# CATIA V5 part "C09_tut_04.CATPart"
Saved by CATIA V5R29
Part number: Part1
Bounding box of the stored display mesh (mm): x -112.5 to 112.5, y -202.31 to 80, z -202.31 to 85
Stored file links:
  C:\Users\CADCIM 00\Desktop\catia parts file\C09\C09_tut_04.CATPart
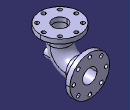
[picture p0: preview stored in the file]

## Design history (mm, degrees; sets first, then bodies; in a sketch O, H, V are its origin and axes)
Body1 (main body)
  Sketch1 on yz-plane, origin (0, 0, 0), H (0, 1, 0), V (0, 0, 1)
    line L1 (-90, 60) -> (-90, 0)
    point P1 (-90, 60)
    arc A1 centre (0, 0) radius 90 from (-90, 0) to (0, -90) ccw
    point P3 (0, 0)
    line L2 (0, -90) -> (55, -90)
    point P5 (55, -90)
    distance P1 L2 = 150
    distance P5 L1 = 145
    radius A1 = 90
    vertical: L1 V
    tangency: A1 L1, L2 A1
    horizontal: L2 H
    coincidence: P3 O
  Plane1: type Normal, Curve Sketch1, RefPoint Sketch1.P5, Ratio 0
  Sketch2 on Plane1, origin (0, 55, 0), H (-1, 0, 0), V (0, 0, 1)
    circle A1 centre (0, -90) radius 48.5
    point P1 (0, -90)
    reference projected point E1 (0, -90) from Sketch1.P5
    radius A1 = 48.5
    coincidence: P1 V, P1 E1
  Rib1: profile Sketch2, centre curve Sketch1, thin wall 16
  Sketch3 on face of Rib1, origin (0, 55, 0), H (-1, 0, 0), V (0, 0, 1)
    circle A1 centre (0, -90) radius 112.5
    point P1 (0, -90)
    reference projected circle E1 centre (0, -90) radius 56.5 from edge [face of Rib1 | face of Rib1]
    circle A2 centre (0, -90) radius 40.5
    reference projected circle E2 centre (0, -90) radius 40.5 from edge [face of Rib1 | face of Rib1]
    radius A1 = 112.5
    coincidence: P1 V, A2 E2
    concentricity: A1 E1
  Pad1: profile Sketch3, direction (0, 1, 0), length 25
  Sketch4 on face of Rib1, origin (0, 0, 60), H (1, 0, 0), V (0, 1, 0)
    circle A1 centre (0, -90) radius 112.5
    point P1 (0, -90)
    reference projected circle E1 centre (0, -90) radius 56.5 from edge [face of Rib1 | face of Rib1]
    circle A2 centre (0, -90) radius 40.5
    reference projected circle E2 centre (0, -90) radius 40.5 from edge [face of Rib1 | face of Rib1]
    radius A1 = 112.5
    coincidence: P1 V, A2 E2
    concentricity: A1 E1
  Pad2: profile Sketch4, direction (0, 0, 1), length 25
  Plane2: type Offset, RefPlane end face of Pad1, Offset 240
  Sketch5 on Plane2, origin (0, -160, 0), H (-1, 0, 0), V (0, 0, 1)
    circle A1 centre (0, -90) radius 25
    point P1 (0, -90)
    reference projected line E1 (-112.5, 85) -> (112.5, 85) from edge [face of Pad2 from Sketch4.A1 | end face of Pad2]
    radius A1 = 25
    distance E1 P1 = 175
    coincidence: P1 V
  Pad3: profile Sketch5, direction (0, 1, 0), up to the existing solid (limit type 2)
  Point1: type Center, Curve edge [start face of Pad3 | face of Pad3 from Sketch5.A1]
  Sketch6 on start face of Pad3, origin (0, -160, -90), H (1, 0, 0), V (0, 0, 1)
    point P1 (0, 0)
    reference projected point E1 (0, 0) from Point1
    coincidence: E1 P1
  Hole1: placed by Sketch6, at (0, -160, -90) direction (0, 1, 0), diameter 20, through (limit type 6), counterbore diameter 24, counterbore depth 28
  Sketch7 on end face of Pad1, origin (0, 80, 0), H (-1, 0, 0), V (0, 0, 1)
    construction circle A1 centre (0, -90) radius 92.5
    point P1 (0, -90)
    reference projected circle E1 centre (0, -90) radius 112.5 from edge [face of Pad1 from Sketch3.A1 | end face of Pad1]
    point P2 (0, 2.5)
    radius A1 = 92.5
    coincidence: P1 V, P2 A1, P2 V
    concentricity: A1 E1
  Sketch8 on end face of Pad1, origin (0, 80, 2.5), H (1, 0, 0), V (0, 0, -1)
    point P1 (0, 0)
    reference projected point E1 (0, 0) from Sketch7.P2
    coincidence: E1 P1
  Hole2: placed by Sketch8, at (0, 80, 2.5) direction (0, -1, 0), diameter 20.5, through (limit type 6)
  CircPattern1: of Hole2, instances 8, angular step 45 {= 360.0*1 deg/CircPattern1.AngularNumber}, axis from face of Pad1
  Sketch9 on end face of Pad2, origin (0, 0, 85), H (1, 0, 0), V (0, 1, 0)
    construction circle A1 centre (0, -90) radius 92.5
    point P1 (0, -90)
    reference projected circle E1 centre (0, -90) radius 112.5 from edge [face of Pad2 from Sketch4.A1 | end face of Pad2]
    point P2 (0, 2.5)
    radius A1 = 92.5
    coincidence: P1 V, P2 A1, P2 V
    concentricity: A1 E1
  Sketch10 on end face of Pad2, origin (0, 2.5, 85), H (1, 0, 0), V (0, 1, 0)
    point P1 (0, 0)
    reference projected point E1 (0, 0) from Sketch9.P2
    coincidence: E1 P1
  Hole3: placed by Sketch10, at (0, 2.5, 85) direction (0, 0, -1), diameter 20.5, through (limit type 6)
  CircPattern2: of Hole3, instances 8, angular step 45 {= 360.0*1 deg/CircPattern2.AngularNumber}, axis from face of Pad2 from Sketch4.A2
